(* Logix 5000 project; controller DNP3Outstation vendor 1 type 14 code 96 rev 21.11; software revision 21.00; part 2 of 2 *)

ADD_ON_INSTRUCTION PSDNP3CounterEvtLog32   (* revision 1.0, vendor ProSoft Technology Inc *)
VAR_IN_OUT
   DNP3Object : PSDNP3Counter32WithFlag; {required}
END_VAR
VAR_INPUT
   Deadband : DINT; {required}
   MinimumLogInterval : REAL; {required}
   ExtrernalEventTrigger : BOOL; {visible}
END_VAR
VAR_OUTPUT
   EventTriggers : DINT; {access Read Only, visible}
END_VAR
VAR
   RequestLog : BOOL; {access None}
   ExternalONS : BOOL; {access None}
   Interval : TIMER := (PRE := 1000000); {access None}
   PreviousValue : DINT; {access None}
   DBRequest : BOOL; {access None}
   ExtRequest : BOOL; {access None}
   Pending : BOOL; {access None}
END_VAR

ROUTINE Logic   (* ladder *)
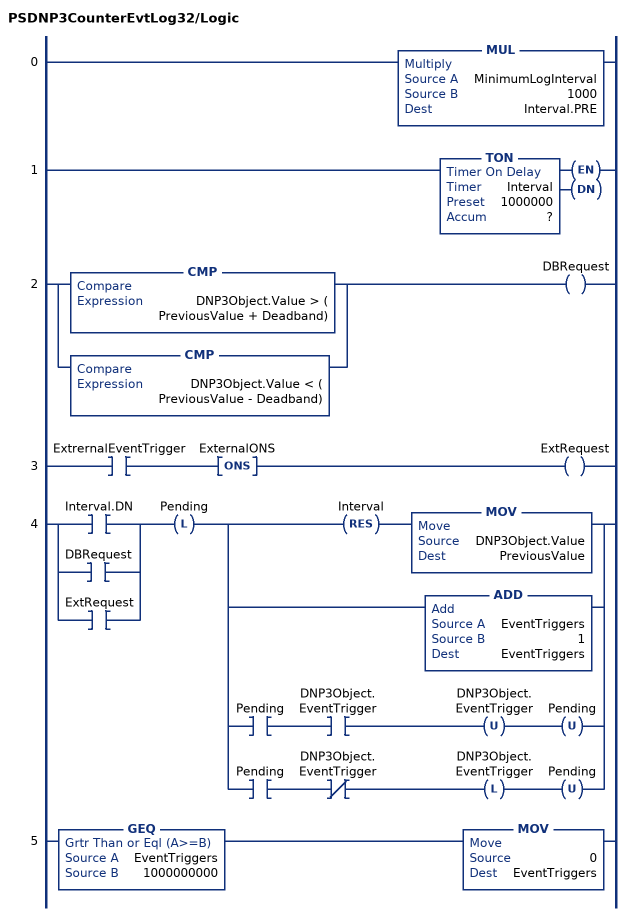
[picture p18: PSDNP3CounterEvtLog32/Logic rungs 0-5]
   0: MUL(MinimumLogInterval,1000,Interval.PRE);
   1: TON(Interval,?,?);
   2: [CMP(DNP3Object.Value > ( PreviousValue + Deadband)) ,CMP(DNP3Object.Value < ( PreviousValue - Deadband)) ]OTE(DBRequest);
   3: XIC(ExtrernalEventTrigger)ONS(ExternalONS)OTE(ExtRequest);
   4: [XIC(Interval.DN) ,XIC(DBRequest) ,XIC(ExtRequest) ]OTL(Pending)[RES(Interval) MOV(DNP3Object.Value,PreviousValue) ,ADD(EventTriggers,1,EventTriggers) ,XIC(Pending) XIC(DNP3Object.EventTrigger) OTU(DNP3Object.EventTrigger) OTU(Pending) ,XIC(Pending) XIO(DNP3Object.EventTrigger) OTL(DNP3Object.EventTrigger) OTU(Pending) ];
   5: GEQ(EventTriggers,1000000000)MOV(0,EventTriggers);
END_ROUTINE
END_ADD_ON_INSTRUCTION

VAR_GLOBAL   (* controller tags *)
   DNP3AnalogOutputRealControl00 : PSDNP3AnalogOutputRealControl := (RequestCount := 37);
   DNP3AnalogOutputRealControl01 : PSDNP3AnalogOutputRealControl := (CurrentOutput := 760.0);
   DNP3BinaryOutputCROB00 : PSDNP3BinaryOutputCROBWithFlag := (CurrentState := 1, LatchOnRequestCount := 1, LatchOffRequestCount := 1, CurrentPulseTarget := 100);
   DNP3BinaryOutputCROB01 : PSDNP3BinaryOutputCROBWithFlag := (CurrentPulseTarget := 100);
   DNP3CounterControl32FlagTime00 : PSDNP3CounterControl32FlagTime := (CurrentCountValue := 17, FrozenCountValue := 95);
   DNP3CounterControl32FlagTime01 : PSDNP3CounterControl32FlagTime := (CurrentCountValue := 11, FrozenCountValue := 124);
   DNP3G01V01 : PSDNP3BinaryInputPacked[10] := ([0].BinaryValues[0] := 9, [0].BinaryValues[1] := 1, [0].BinaryValues[2] := 1, [0].BinaryValues[3] := -64);
   DNP3G01V02 : PSDNP3BinaryInputWithFlag[100];
   DNP3G03V01 : PSDNP3DoubleBinaryInputPacked[10];
   DNP3G03V02 : PSDNP3DoubleBinaryInputWithFlag[10] := ([0].Online := 1, [0].LocalForced := 1, [0].State0 := 1, [0].State1 := 1, [1].Online := 1, [1].State1 := 1);
   DNP3G10V01 : PSDNP3BinaryOutputPacked[10];
   DNP3G10V02 : PSDNP3BinaryOutputWithFlag[10] := ([0].Online := 1, [0].LocalForced := 1, [0].Reserved2 := 1, [0].State := 1, [1].Online := 1, [1].Restart := 1);
   DNP3G110V01 : STRING[10];
   DNP3G12V01 : PSDNP3CROB[10] := ([3].RequestPending := 1, [3].ControlCode := 3, [3].Count := 1, [3].OnTime := 100, [3].OffTime := 100);
   DNP3G20V01 : PSDNP3Counter32WithFlag[10];
   DNP3G20V01AnalogInputEvtLog00 : PSDNP3CounterEvtLog32;
   DNP3G20V01Ctrl : PSDNP3CounterCtrl[10];
   DNP3G20V02 : PSDNP3Counter16WithFlag[10];
   DNP3G20V02Ctrl : PSDNP3CounterCtrl[10];
   DNP3G20V05 : DINT[10] := ([0] := 143, [1] := 144, [2] := 145, [3] := 146, [4] := 147, [5] := 148, [6] := 149, [7] := 150, [8] := 151, [9] := 152);
   DNP3G20V05Ctrl : PSDNP3CounterCtrl[10];
   DNP3G20V06 : INT[10] := ([0] := 6, [1] := 154, [2] := 155, [3] := 156, [4] := 157, [5] := 158, [6] := 159, [7] := 160, [8] := 161, [9] := 162);
   DNP3G20V06Ctrl : PSDNP3CounterCtrl[10];
   DNP3G21V01 : PSDNP3FrozenCounter32WithFlag[10] := ([0].LocalForced := 1, [0].Value := 88, [1].Online := 1, [1].Value := 324, [2].Restart := 1, [2].CommLost := 1, [2].Value := 100268, [9].Online := 1, [9].Value := 123456789);
   DNP3G21V02 : PSDNP3FrozenCounter16WithFlag[10] := ([0].Online := 1, [0].Value := 32000, [5].Restart := 1, [5].CommLost := 1, [5].Value := 31000);
   DNP3G21V05 : PSDNP3FrozenCounter32WithFlagTime[100];
   DNP3G21V06 : PSDNP3FrozenCounter16WithFlagTimeRev2[10] := ([0].Online := 1, [0].Value := 3);
   DNP3G21V09 : DINT[10];
   DNP3G21V10 : INT[10] := ([0] := 6);
   DNP3G30V01 : PSDNP3AnalogInput32Flag[10];
   DNP3G30V02 : PSDNP3AnalogInput16Flag[10];
   DNP3G30V03 : DINT[200];
   DNP3G30V04 : INT[10];
   DNP3G30V05 : PSDNP3AnalogInputRealFlag[100];
   DNP3G30V05AnalogInputEvtLog00 : PSDNP3AnalogInputEvtLogReal := (Deadband := 12.0, MinimumLogInterval := 120.0, EventTriggers := 26);
   DNP3G40V01 : PSDNP3AnalogOutputStatus32Flag[10] := ([0].Online := 1, [0].Value := 56, [9].Online := 1, [9].Value := 1512);
   DNP3G40V02 : PSDNP3AnalogOutputStatus16Flag[10] := ([0].Online := 1, [0].Value := 123, [9].Value := 667);
   DNP3G40V03 : PSDNP3AnalogOutputStatusRealFlag[10] := ([0].Online := 1, [1].Online := 1, [1].Value := 760.0, [9].Online := 1, [9].Value := 234.654);
   DNP3G40V03AnalogOutputStatusEvtLog00 : PSDNP3AnalogOutputStatusEvtLogReal;
   DNP3G41V01 : PSDNP3AnalogOutput32[10] := ([0].Value := 56, [7].RequestPending := 1, [7].Value := 77);
   DNP3G41V02 : PSDNP3AnalogOutput16[10] := ([0].Value := 123);
   DNP3G41V03 : PSDNP3AnalogOutputReal[10];
   DNP3ResetStatistics : BOOL;
   DNP3ResetStatisticsRequest : BOOL;
   DNP3TimeNeeded : SINT := 1;
   DNP3TimeNeededMsg : MESSAGE;
        MessageParameters(ServiceCode := 16#0010, LocalElement := DNP3TimeNeeded, ...)
   DummyAnalogInput00 : REAL := 420.0;
   DummyAnalogInput01 : REAL := 25.7;
   DummyAnalogOutput00 : REAL;
   DummyAnalogOutput01 : REAL := 760.0;
   DummyBinaryInput00 : BOOL;
   DummyBinaryInput01 : BOOL;
   DummyCounter00 : COUNTER := (PRE := 123);
   DummyCounter01 : COUNTER := (PRE := 123);
   DummyCounterPulse00 : BOOL := 1;
   DummyCounterPulse01 : BOOL := 1;
   DummyDoubleBinaryInput00_0 : BOOL := 1;
   DummyDoubleBinaryInput00_1 : BOOL := 1;
   DummyDoubleBinaryInput01_0 : BOOL;
   DummyDoubleBinaryInput01_1 : BOOL := 1;
   DummyOutput00 : BOOL := 1;
   DummyOutput01 : BOOL;
   PLX51DNPSInput : PLX51DNPInput;
   PLX51DNPSOutput : PLX51DNPOutput;
   SetDNP3TimeNeeded : BOOL;
   ShiftCounter : PSDNP3Counter32WithFlag[10];
   ShiftCounterCtrl : PSDNP3CounterCtrl[10];
END_VAR

PROGRAM DNP3Outstation   (* main routine MainRoutine *)

ROUTINE AnalogInputs   (* ladder *)
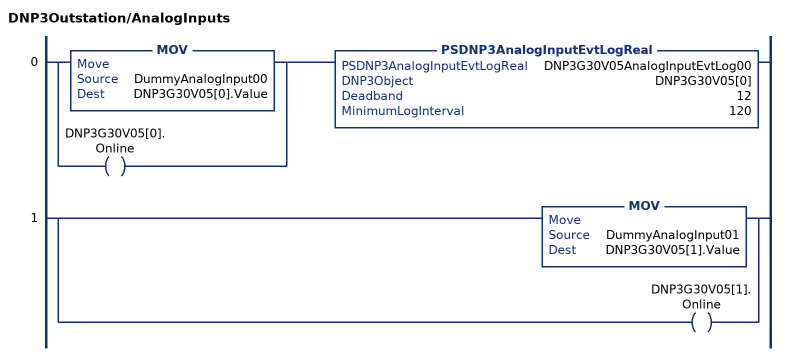
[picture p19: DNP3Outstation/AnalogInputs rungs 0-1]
   0: [MOV(DummyAnalogInput00,DNP3G30V05[0].Value) ,OTE(DNP3G30V05[0].Online) ]PSDNP3AnalogInputEvtLogReal(DNP3G30V05AnalogInputEvtLog00,DNP3G30V05[0],12,120);
   1: [MOV(DummyAnalogInput01,DNP3G30V05[1].Value) ,OTE(DNP3G30V05[1].Online) ];
END_ROUTINE

ROUTINE AnalogOutputs   (* ladder *)
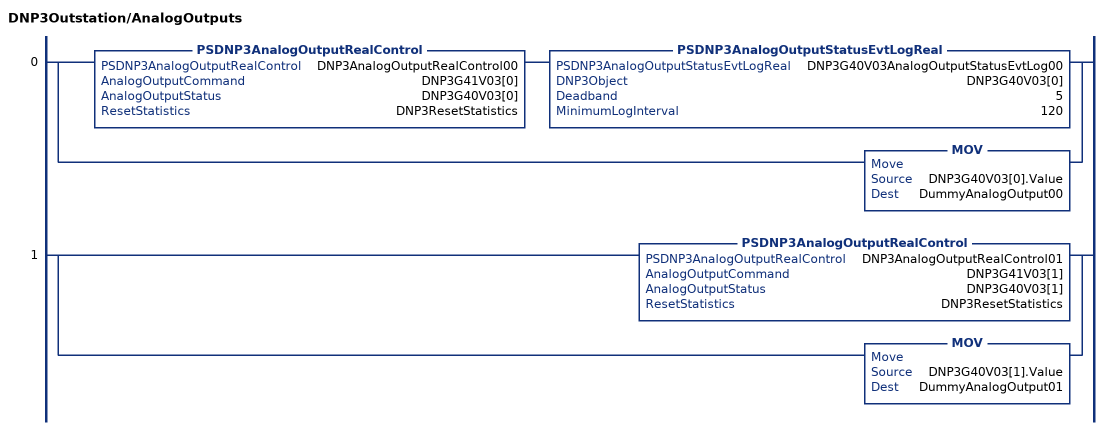
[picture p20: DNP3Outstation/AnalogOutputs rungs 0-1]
   0: [PSDNP3AnalogOutputRealControl(DNP3AnalogOutputRealControl00,DNP3G41V03[0],DNP3G40V03[0],DNP3ResetStatistics) PSDNP3AnalogOutputStatusEvtLogReal(DNP3G40V03AnalogOutputStatusEvtLog00,DNP3G40V03[0],5,120) ,MOV(DNP3G40V03[0].Value,DummyAnalogOutput00) ];
   1: [PSDNP3AnalogOutputRealControl(DNP3AnalogOutputRealControl01,DNP3G41V03[1],DNP3G40V03[1],DNP3ResetStatistics) ,MOV(DNP3G40V03[1].Value,DummyAnalogOutput01) ];
END_ROUTINE

ROUTINE BinaryInputs   (* ladder *)
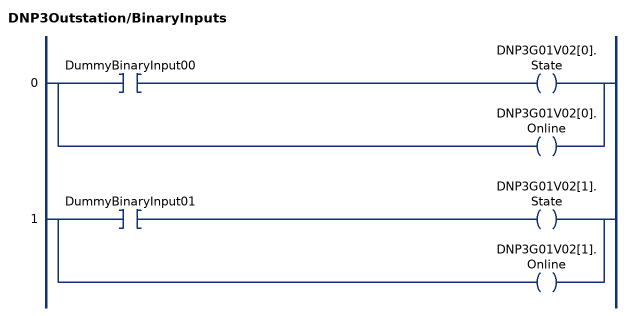
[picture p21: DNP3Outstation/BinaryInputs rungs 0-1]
   0: [XIC(DummyBinaryInput00) OTE(DNP3G01V02[0].State) ,OTE(DNP3G01V02[0].Online) ];
   1: [XIC(DummyBinaryInput01) OTE(DNP3G01V02[1].State) ,OTE(DNP3G01V02[1].Online) ];
END_ROUTINE

ROUTINE BinaryOutputs   (* ladder *)
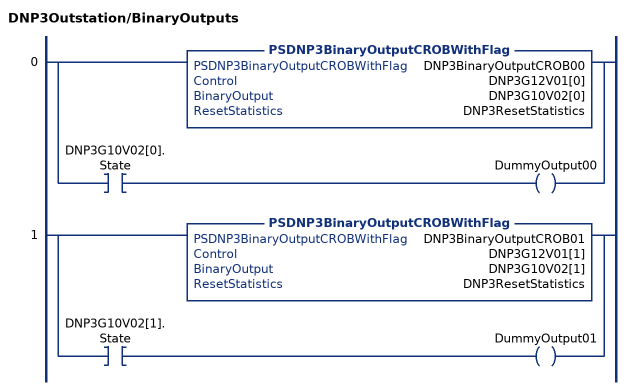
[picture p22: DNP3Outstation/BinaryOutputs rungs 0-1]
   0: [PSDNP3BinaryOutputCROBWithFlag(DNP3BinaryOutputCROB00,DNP3G12V01[0],DNP3G10V02[0],DNP3ResetStatistics) ,XIC(DNP3G10V02[0].State) OTE(DummyOutput00) ];
   1: [PSDNP3BinaryOutputCROBWithFlag(DNP3BinaryOutputCROB01,DNP3G12V01[1],DNP3G10V02[1],DNP3ResetStatistics) ,XIC(DNP3G10V02[1].State) OTE(DummyOutput01) ];
END_ROUTINE

ROUTINE Counters   (* ladder *)
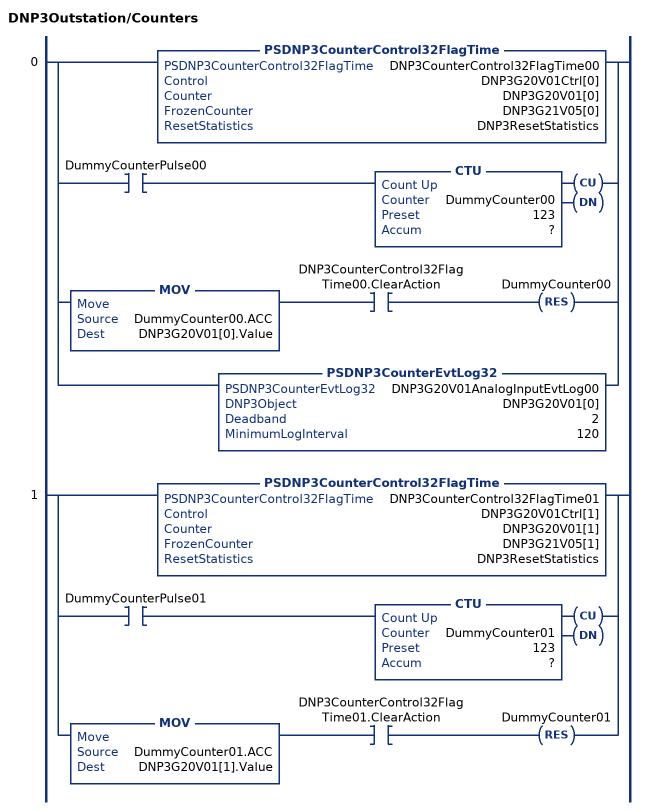
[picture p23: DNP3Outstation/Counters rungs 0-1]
   0: [PSDNP3CounterControl32FlagTime(DNP3CounterControl32FlagTime00,DNP3G20V01Ctrl[0],DNP3G20V01[0],DNP3G21V05[0],DNP3ResetStatistics) ,XIC(DummyCounterPulse00) CTU(DummyCounter00,?,?) ,MOV(DummyCounter00.ACC,DNP3G20V01[0].Value) XIC(DNP3CounterControl32FlagTime00.ClearAction) RES(DummyCounter00) ,PSDNP3CounterEvtLog32(DNP3G20V01AnalogInputEvtLog00,DNP3G20V01[0],2,120) ];
   1: [PSDNP3CounterControl32FlagTime(DNP3CounterControl32FlagTime01,DNP3G20V01Ctrl[1],DNP3G20V01[1],DNP3G21V05[1],DNP3ResetStatistics) ,XIC(DummyCounterPulse01) CTU(DummyCounter01,?,?) ,MOV(DummyCounter01.ACC,DNP3G20V01[1].Value) XIC(DNP3CounterControl32FlagTime01.ClearAction) RES(DummyCounter01) ];
END_ROUTINE

ROUTINE DoubleBinaryInputs   (* ladder *)
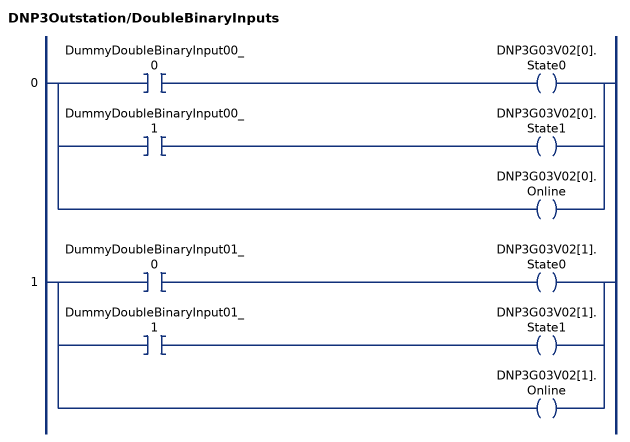
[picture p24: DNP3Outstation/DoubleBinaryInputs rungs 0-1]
   0: [XIC(DummyDoubleBinaryInput00_0) OTE(DNP3G03V02[0].State0) ,XIC(DummyDoubleBinaryInput00_1) OTE(DNP3G03V02[0].State1) ,OTE(DNP3G03V02[0].Online) ];
   1: [XIC(DummyDoubleBinaryInput01_0) OTE(DNP3G03V02[1].State0) ,XIC(DummyDoubleBinaryInput01_1) OTE(DNP3G03V02[1].State1) ,OTE(DNP3G03V02[1].Online) ];
END_ROUTINE

ROUTINE MainRoutine   (* ladder *)
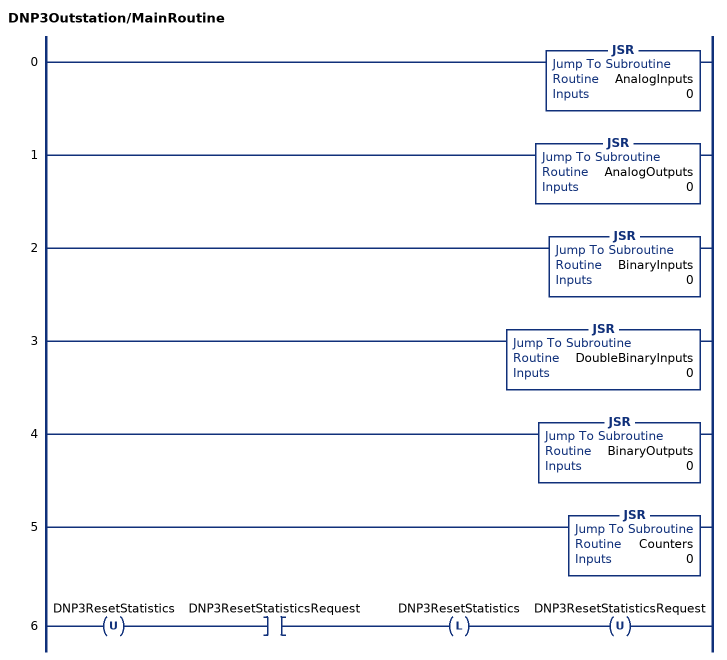
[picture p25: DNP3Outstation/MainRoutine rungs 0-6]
   0: JSR(AnalogInputs,0);
   1: JSR(AnalogOutputs,0);
   2: JSR(BinaryInputs,0);
   3: JSR(DoubleBinaryInputs,0);
   4: JSR(BinaryOutputs,0);
   5: JSR(Counters,0);
   6: OTU(DNP3ResetStatistics)XIC(DNP3ResetStatisticsRequest)OTL(DNP3ResetStatistics)OTU(DNP3ResetStatisticsRequest);
END_ROUTINE

ROUTINE Services   (* ladder *)
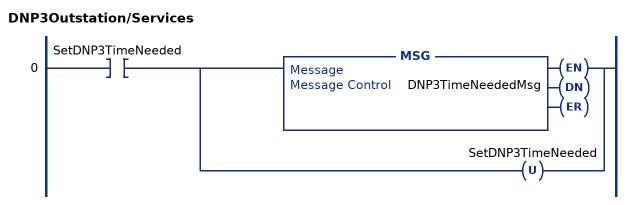
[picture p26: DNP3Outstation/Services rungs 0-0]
   0: XIC(SetDNP3TimeNeeded)[MSG(DNP3TimeNeededMsg) ,OTU(SetDNP3TimeNeeded) ];
END_ROUTINE
END_PROGRAM
